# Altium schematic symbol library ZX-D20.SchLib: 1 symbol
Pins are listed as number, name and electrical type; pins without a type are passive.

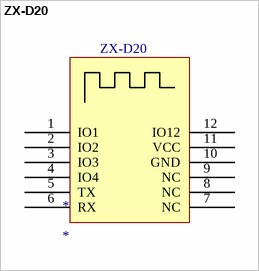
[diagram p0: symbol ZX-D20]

## ZX-D20
designator *
pins: 1 IO1 "AT选择引脚", 2 IO2 "状态引脚", 3 IO3 "按键引脚", 4 IO4 "LED灯引脚", 5 TX "串口输出", 6 RX "串口输入", 7 NC "悬空", 8 NC "悬空", 9 NC "悬空", 10 GND "地", 11 VCC "电源(3.1-4.35V)", 12 IO12 "定制输入输出引脚"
